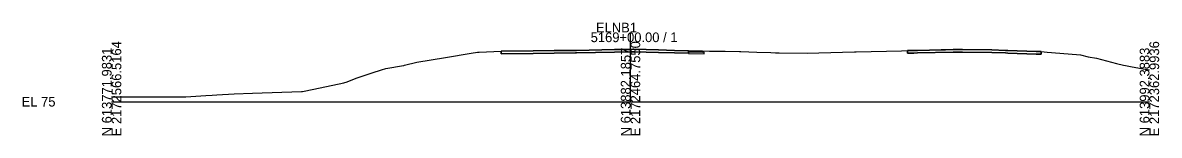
# Model space of a CAD drawing. Extents: x -26 to 1303, y -3010 to 12038.
# Drawn here: x -25.7 to 302.8, y -1509.7 to -1477.2 of the extents above; entities that cross this region are included whole.
import ezdxf

# ---------------------------------------------------------------- set-up
doc = ezdxf.new("R2010")
doc.units = 0
for name, color, linetype in [('RD_GPK_XS_Cell', 7, 'Continuous'), ('RD_XS_Base', 7, 'Continuous'), ('RD_XS_ExGround', 7, 'Continuous'), ('RD_XS_ExPaveRet', 7, 'Continuous'), ('RD_XS_Pave', 7, 'Continuous'), ('RD_XS_PaveOvlay_CP', 7, 'Continuous')]:
    doc.layers.add(name, color=color, linetype=linetype)

msp = doc.modelspace()

# ---------------------------------------------------------------- linework, layer by layer
at = {"layer": 'RD_GPK_XS_Cell'}
for p, q in [((150, -1500), (150, -1480)), ((0, -1500), (150, -1500)), ((150, -1500), (300, -1500))]:
    msp.add_line(p, q, dxfattribs=at)
at = {"layer": 'RD_XS_Base'}
for p, q in [((166.75, -1486.03), (166.75, -1486.1)), ((166.75, -1486.1), (171.26, -1486.18)), ((170.77, -1485.67), (166.76, -1485.6)), ((171.26, -1485.68), (170.77, -1485.67)), ((171.26, -1486.18), (171.26, -1485.68)), ((171.26, -1485.78), (171.26, -1485.78))]:
    msp.add_line(p, q, dxfattribs=at)
at = {"layer": 'RD_XS_ExGround'}
msp.add_lwpolyline([(0, -1498.59), (21.46, -1498.59), (27.27, -1498.24), (29.05, -1498.14), (30.44, -1498.04), (35.43, -1497.73), (40.71, -1497.51), (54.91, -1497.08), (55.21, -1497.06), (58.49, -1496.37), (67.16, -1494.55), (68.07, -1494.24), (70.65, -1493.21), (75.33, -1491.66), (77.97, -1490.77), (79.23, -1490.45), (84.42, -1489.54), (84.5, -1489.51), (84.65, -1489.48), (88.26, -1488.54), (96.52, -1487.19), (103.97, -1485.96), (105.79, -1485.67), (106.23, -1485.68), (112.63, -1485.42), (128.28, -1485.26), (134.39, -1485.18), (145.27, -1484.97), (150.99, -1484.86), (158.06, -1485.05), (166.75, -1485.28), (172.87, -1485.39), (177.32, -1485.43), (181.52, -1485.5), (181.86, -1485.5), (186.49, -1485.66), (190.56, -1485.82), (191.86, -1485.86), (192.93, -1485.88), (201.04, -1485.94), (204.39, -1485.93), (214.71, -1485.64), (215.18, -1485.63), (228.32, -1485.3), (230.1, -1485.25), (231.33, -1485.22), (245.93, -1484.9), (254.48, -1485.07), (259.06, -1485.2), (268.68, -1485.53), (270.43, -1485.69), (271.68, -1485.78), (280.04, -1486.5), (282.3, -1487), (284.7, -1487.47), (290.47, -1488.97), (292.48, -1489.46), (293.05, -1489.5), (294.48, -1489.85), (298.23, -1490.49), (300, -1490.78)], dxfattribs=at)
at = {"layer": 'RD_XS_ExPaveRet'}
for points in [[(166.75, -1485.28), (166.75, -1485.28), (166.75, -1485.51), (166.75, -1486.03), (166.75, -1486.03), (162.74, -1485.92), (158.06, -1485.8), (151, -1485.61), (150.99, -1485.61), (150.69, -1485.62), (150, -1485.63), (145.41, -1485.71), (134.39, -1485.93), (134.13, -1485.93), (127.95, -1486.01), (121.85, -1486.07), (112.63, -1486.17), (112.63, -1485.64), (112.63, -1485.42), (121.85, -1485.32), (127.95, -1485.26), (134.13, -1485.18), (134.39, -1485.18), (145.41, -1484.96), (150, -1484.88), (150.69, -1484.87), (150.99, -1484.86), (151, -1484.86), (158.06, -1485.05), (162.74, -1485.17), (166.75, -1485.28)], [(162.74, -1485.17), (158.06, -1485.05), (151, -1484.86), (150.99, -1484.86), (150.69, -1484.87), (150, -1484.88), (145.41, -1484.96), (134.39, -1485.18), (134.13, -1485.18), (127.95, -1485.26), (121.85, -1485.32), (112.63, -1485.42), (112.63, -1485.64), (112.63, -1486.17), (121.85, -1486.07), (127.95, -1486.01), (134.13, -1485.93), (134.39, -1485.93), (145.41, -1485.71), (150, -1485.63), (150.69, -1485.62), (150.99, -1485.61), (151, -1485.61), (158.06, -1485.8), (162.74, -1485.92), (166.75, -1486.03), (166.75, -1485.51), (166.75, -1485.28), (162.74, -1485.17)], [(268.68, -1485.53), (268.68, -1485.53), (268.68, -1486.11), (268.68, -1486.28), (268.68, -1486.28), (268.68, -1486.28), (268.68, -1486.28), (267.3, -1486.24), (259.06, -1485.95), (258.41, -1485.93), (254.48, -1485.82), (245.94, -1485.65), (245.93, -1485.65), (245.92, -1485.65), (243.31, -1485.71), (232.99, -1485.93), (231.89, -1485.95), (230.1, -1486), (230.1, -1485.42), (230.1, -1485.25), (231.89, -1485.2), (232.99, -1485.18), (243.31, -1484.96), (245.92, -1484.9), (245.93, -1484.9), (245.94, -1484.9), (254.48, -1485.07), (258.41, -1485.18), (259.06, -1485.2), (267.3, -1485.49), (268.68, -1485.53), (268.68, -1485.53), (268.68, -1485.53)], [(268.68, -1485.53), (268.68, -1485.53), (267.3, -1485.49), (259.06, -1485.2), (258.41, -1485.18), (254.48, -1485.07), (245.94, -1484.9), (245.93, -1484.9), (245.92, -1484.9), (243.31, -1484.96), (232.99, -1485.18), (231.89, -1485.2), (230.1, -1485.25), (230.1, -1485.42), (230.1, -1486), (231.89, -1485.95), (232.99, -1485.93), (243.31, -1485.71), (245.92, -1485.65), (245.93, -1485.65), (245.94, -1485.65), (254.48, -1485.82), (258.41, -1485.93), (259.06, -1485.95), (267.3, -1486.24), (268.68, -1486.28), (268.68, -1486.28)], [(268.68, -1486.28), (268.68, -1486.11), (268.68, -1485.53)], [(268.68, -1485.53), (268.68, -1485.53)], [(268.68, -1486.28), (268.68, -1486.28)]]:
    msp.add_lwpolyline(points, dxfattribs=at)
at = {"layer": 'RD_XS_Pave'}
for p, q in [((170.76, -1485.36), (166.75, -1485.28)), ((170.77, -1485.52), (166.75, -1485.44)), ((166.75, -1485.44), (170.77, -1485.52)), ((166.76, -1485.6), (170.77, -1485.67)), ((170.76, -1485.52), (170.76, -1485.36)), ((170.76, -1485.44), (170.76, -1485.44)), ((170.76, -1485.67), (170.76, -1485.52)), ((170.76, -1485.6), (170.76, -1485.6))]:
    msp.add_line(p, q, dxfattribs=at)
at = {"layer": 'RD_XS_PaveOvlay_CP'}
msp.add_line((170.76, -1485.36), (166.75, -1485.28), dxfattribs=at)

# ---------------------------------------------------------------- texts
at = {"layer": 'RD_GPK_XS_Cell'}
for s, p in [('ELNB1', (140, -1480)), ('5169+00.00 / 1', (138.48, -1482.8)), ('EL 75', (-26, -1501.4))]:
    msp.add_text(s, height=2.8, dxfattribs=at).set_placement(p)
for s, p in [('N 613771.9831', (0, -1510)), ('E 2172566.5164', (2.8, -1510)), ('N 613882.1857', (150, -1510)), ('E 2172464.7550', (152.8, -1510)), ('N 613992.3883', (300, -1510)), ('E 2172362.9936', (302.8, -1510))]:
    msp.add_text(s, height=2.8, rotation=90, dxfattribs=at).set_placement(p)

doc.saveas('drawing.dxf')
